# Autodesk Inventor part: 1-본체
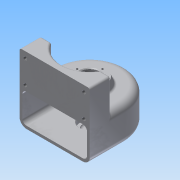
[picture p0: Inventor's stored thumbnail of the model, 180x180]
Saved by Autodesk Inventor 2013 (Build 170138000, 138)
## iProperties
Created: 2015-02
Part Number: 1-본체
Material: 알루미늄 6061
Document SubType Name: Modeling
Designer: Administrator
Density: 2.40731 g/cm^3
Mass: 511.093 g
Surface Area: 706.387 cm^2
Volume: 212.309 cm^3
Author: Administrator
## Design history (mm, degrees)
sketch "스케치1"
  geometry: L1 (-50, 0)-(-50, -50); L2 (-50, -50)-(50, -50); L3 (50, -50)-(50, 0); A1 r 50 centre (0, 0) between (50, 0) and (-50, 0); 1 further point
  constraints: 6 end point, 2 point on circle, 2 tangent, 1 centre point, 1 coincident, 1 parallel, 1 perpendicular, 1 vertical
  dimensions: "d0" = 50 radius of A1; "d2" = 50 distance of L3.end L2.end
extrude "돌출1" new body sketch "스케치1" distance "d3" = 50; taper "d4" = 0 deg
feature "쉘2" dims "d34" = 4
sketch "스케치2"
  geometry: C1 r 25 at (0, 0); A1 r 50 centre (0, 0) between (50, 0) and (-50, 0) reference
  constraints: 1 centre point, 1 coincident
  dimensions: "d5" = 50 diameter of C1
extrude "돌출2" join sketch "스케치2" distance "d7" = 10; taper "d8" = -20 deg
node "작업 평면1"
sketch "스케치5"
  geometry: C1 r 20 at (0, 0); 1 further point
  constraints: 1 centre point, 1 coincident
  dimensions: "d55" = 40 diameter of C1
extrude "돌출4" join sketch "스케치5" distance "d57" = 9; taper "d58" = 0 deg
hole "구멍5" diameter "d61" = 20; stored, may be unused: countersink angle "d65" = 90 deg, drill point angle "d67" = 0 deg; dims "d59" = 10, "d60" = 10, "d62" = 6, "d63" = 28, "d64" = 8, "d66" = 10
hole "구멍3" diameter "d37" = 20; stored, may be unused: countersink angle "d41" = 90 deg, drill point angle "d43" = 0 deg; dims "d35" = 10, "d36" = 10, "d38" = 6, "d39" = 28, "d40" = 10, "d42" = 14
fillet "모깎기1" dims "d53" = 10
node "작업 평면2"
sketch "스케치7"
  geometry: L1 (50, -50)-(50, 0) reference; L2 (40, 0)-(40, -50) reference; L3 (-40, -50)-(-40, 0) reference; L4 (-40, -50)-(40, -50) reference; L5 (-46, 0)-(-46, -50) reference; L6 (-50, 0)-(-50, -50) reference; L7 (34.641, -20)-(50, -20); L8 (34.641, -20)-(34.641, -50); L9 (50, -50)-(34.641, -50); L10 (50, -20)-(50, -50); L11 (-34.641, -20)-(-34.641, -50); L12 (-34.641, -20)-(-50, -20); L13 (-50, -20)-(-50, -50); L14 (-34.641, -50)-(-50, -50); L15 (-34.641, -50)-(34.641, -50); C1 r 25 at (0, 0) reference; A1 r 40 centre (0, 0) between (40, 0) and (-40, 0) reference; A2 r 50 centre (0, 0) between (50, 0) and (-50, 0) reference; A3 r 40 centre (0, 0) between (34.641, -20) and (-34.641, -20); 1 further point
  constraints: 18 end point, 5 collinear, 4 perpendicular, 4 point on line, 2 point on circle, 1 centre point, 1 coincident, 1 parallel
  dimensions: "d69" = 40 radius of A3; "d71" = 30 distance between parallel lines of L9 L7
extrude "돌출5" join sketch "스케치7" stored distance "d72" = 9; taper "d73" = 0 deg
sketch "스케치8"
  geometry: L1 (100, 10)-(100, 95) reference; L2 (0, 95)-(100, 95) reference; L3 (8.25, 53)-(91.75, 53); L4 (91.75, 53)-(91.75, 86); L5 (91.75, 86)-(8.25, 86); L6 (8.25, 86)-(8.25, 53); L7 (8.25, 53)-(91.75, 86); L8 (91.75, 53)-(8.25, 86); 7 further points
  constraints: 12 end point, 4 coincident, 2 midpoint, 2 parallel, 1 horizontal, 1 perpendicular
  dimensions: "d74" = 33 distance of L3.end L4.end; "d76" = 9 distance between parallel lines of L2 L5; "d77" = 83.5 distance of L4.end L5.end; "d78" = 8.25 distance between parallel lines of L4 L1
hole "구멍6" sketch "스케치8" at (91.75, 86), (91.75, 53), (8.25, 53), (8.25, 86) diameter "d79" = 5.134; stored, may be unused: countersink angle "d83" = 90 deg, drill point angle "d85" = 118 deg; dims "d80" = 10, "d81" = 28, "d82" = 8, "d84" = 13
fillet "모깎기2" dims "d86" = 6
sketch "스케치9"
  geometry: C1 r 14 at (0, 0) reference; C2 r 21.36 at (0, 0) reference; A1 r 18 centre (0, 0) between (0, 18) and (0, -18); 2 further points
  constraints: 4 point on circle, 2 horizontal alignment, 2 vertical alignment, 1 centre point, 1 coincident
  dimensions: "d87" = 36 diameter of A1
hole "구멍7" sketch "스케치9" at (0, 18), (0, -18), (18, 0), (-18, 0) diameter "d89" = 2.459; stored, may be unused: countersink angle "d93" = 90 deg, drill point angle "d95" = 118 deg; dims "d90" = 6, "d91" = 28, "d92" = 8, "d94" = 9
fillet "모깎기3" dims "d96" = 3
fillet "모깎기4" dims "d97" = 3
chamfer "모따기1" distance "d98" = 1; stored, may be unused: second distance "d99" = 2, angle "d100" = 45 deg
fillet "모깎기5" dims "d101" = 0.3
fillet "모깎기6" dims "d102" = 3
node "작업 평면3"
sketch "스케치10"
  geometry: L1 (40, 0)-(-40, 0) reference; 2 further points
  constraints: 1 vertical alignment, 1 other
  dimensions: "d103" = 25 distance from line of L1 point (0, 25)
feature "엠보싱1" sketch "스케치10" dims "d0" = 50, "d2" = 50, "d104" = 0.5, "d105" = 0
node "솔리드1"
node "투영된 루프1"
other parameters: "d54" = 9, "d68" = 95
